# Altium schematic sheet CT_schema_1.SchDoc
size 631 x 630 mm
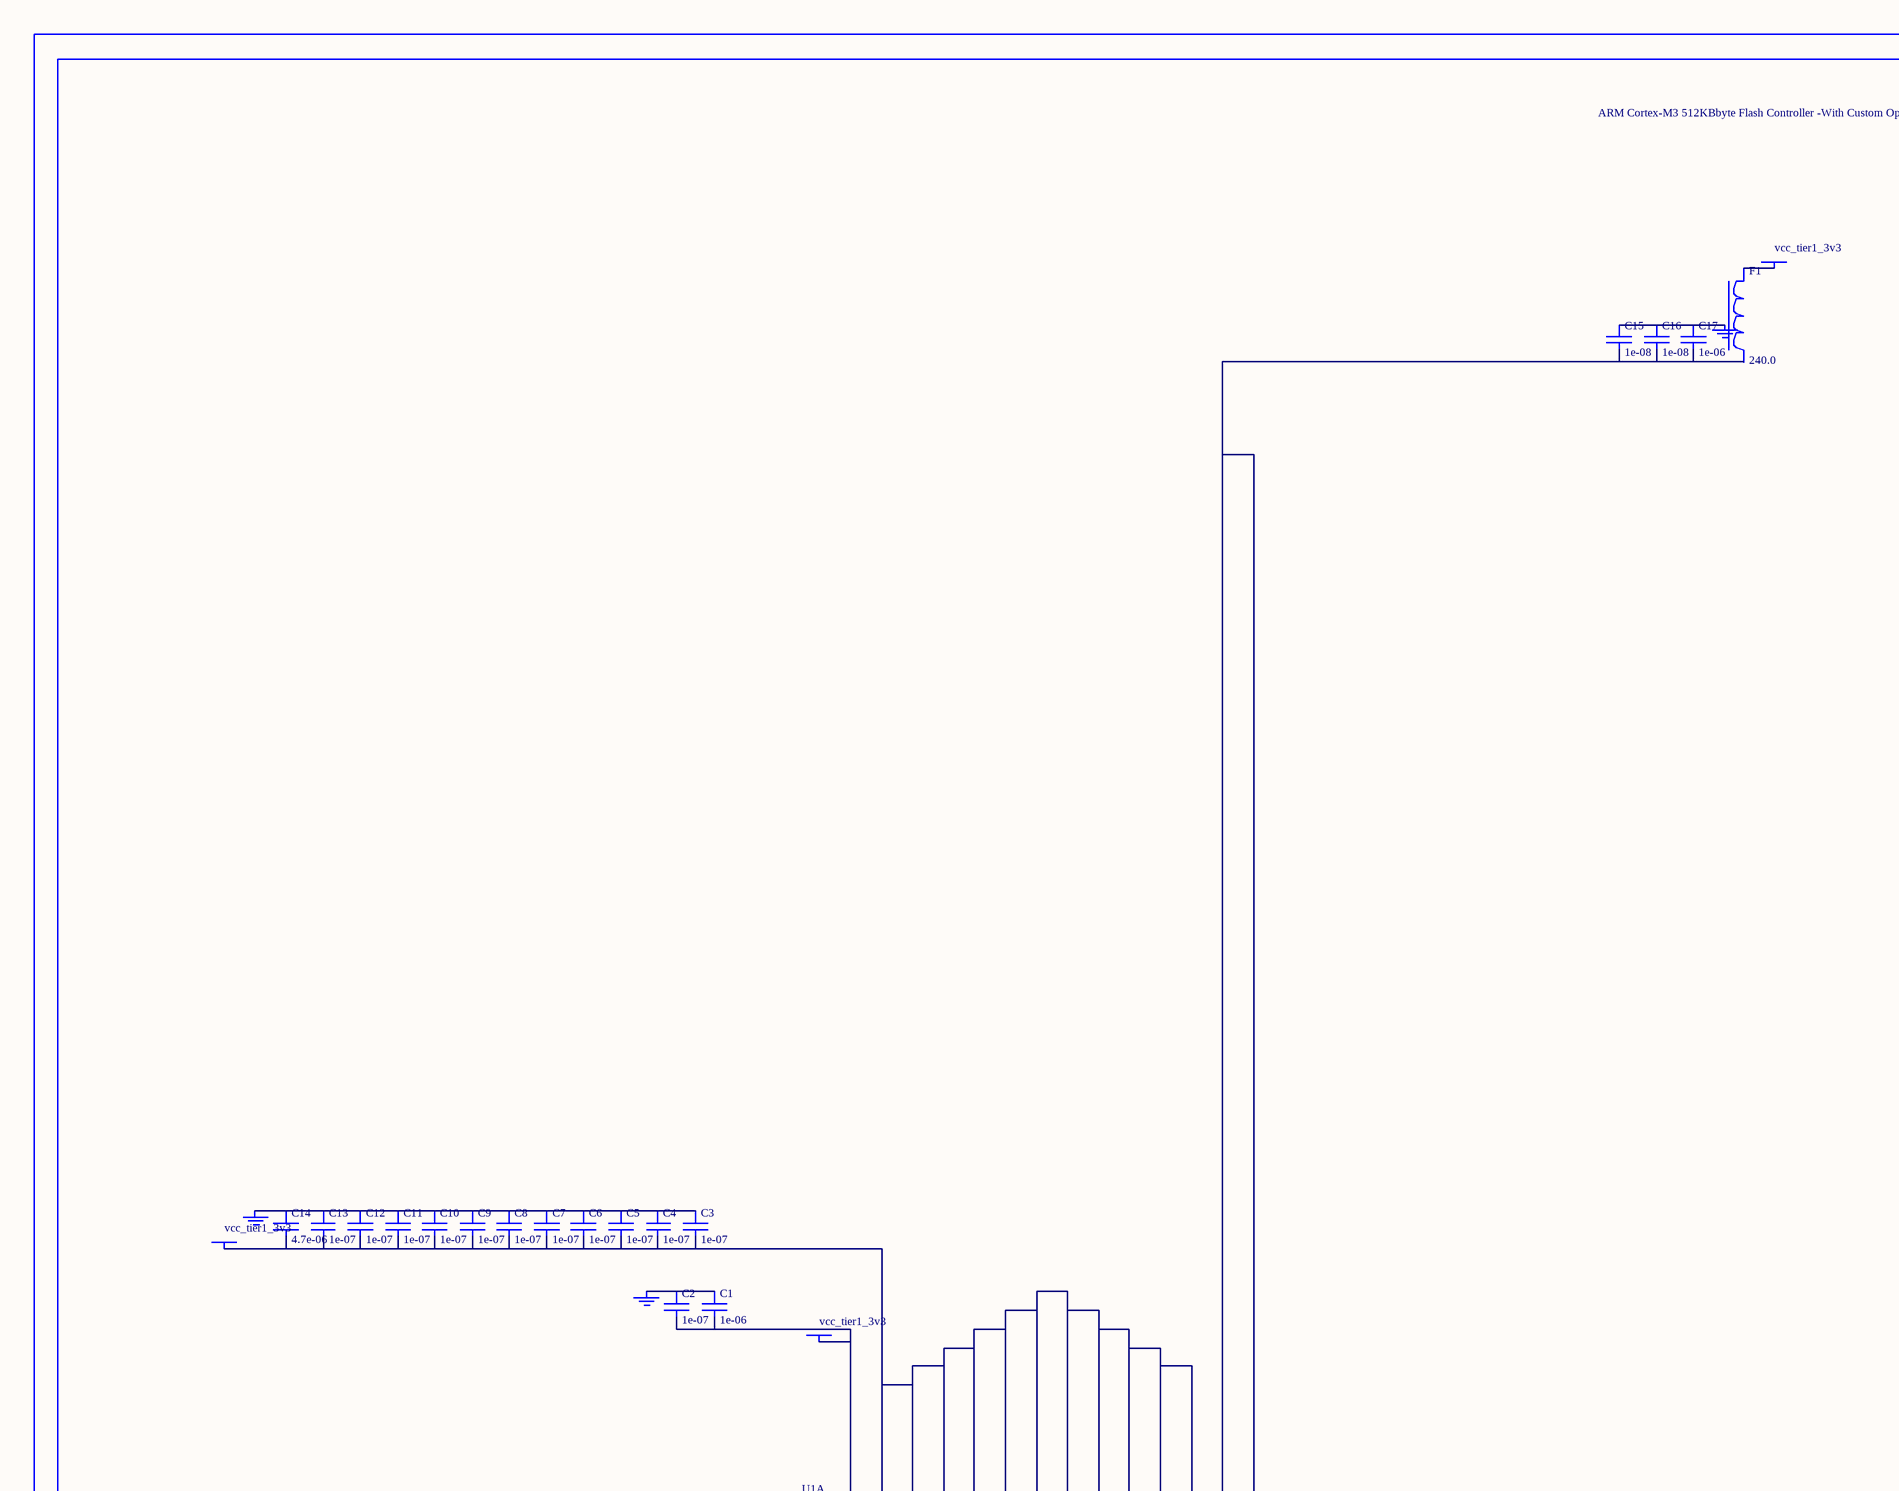
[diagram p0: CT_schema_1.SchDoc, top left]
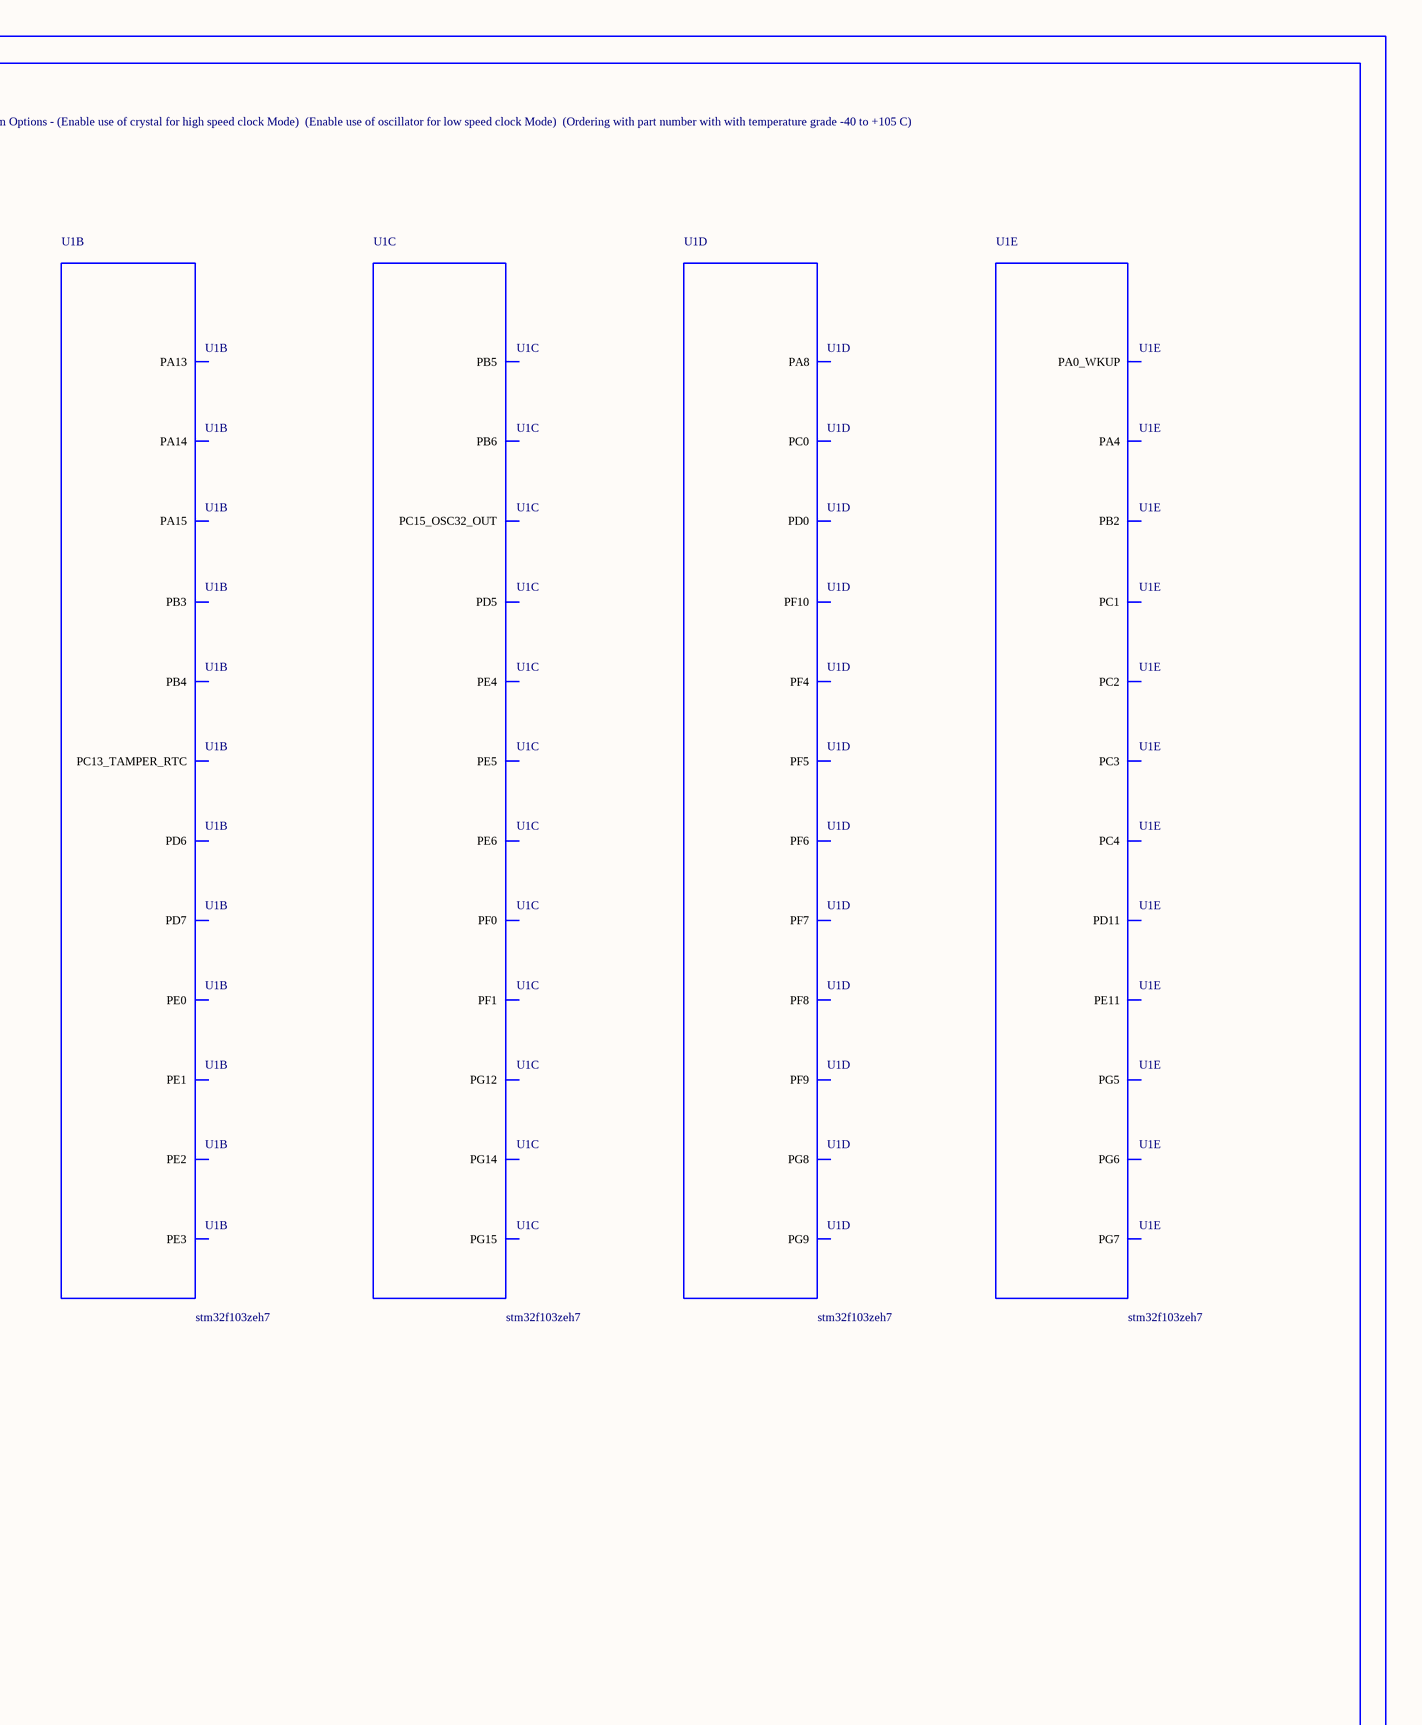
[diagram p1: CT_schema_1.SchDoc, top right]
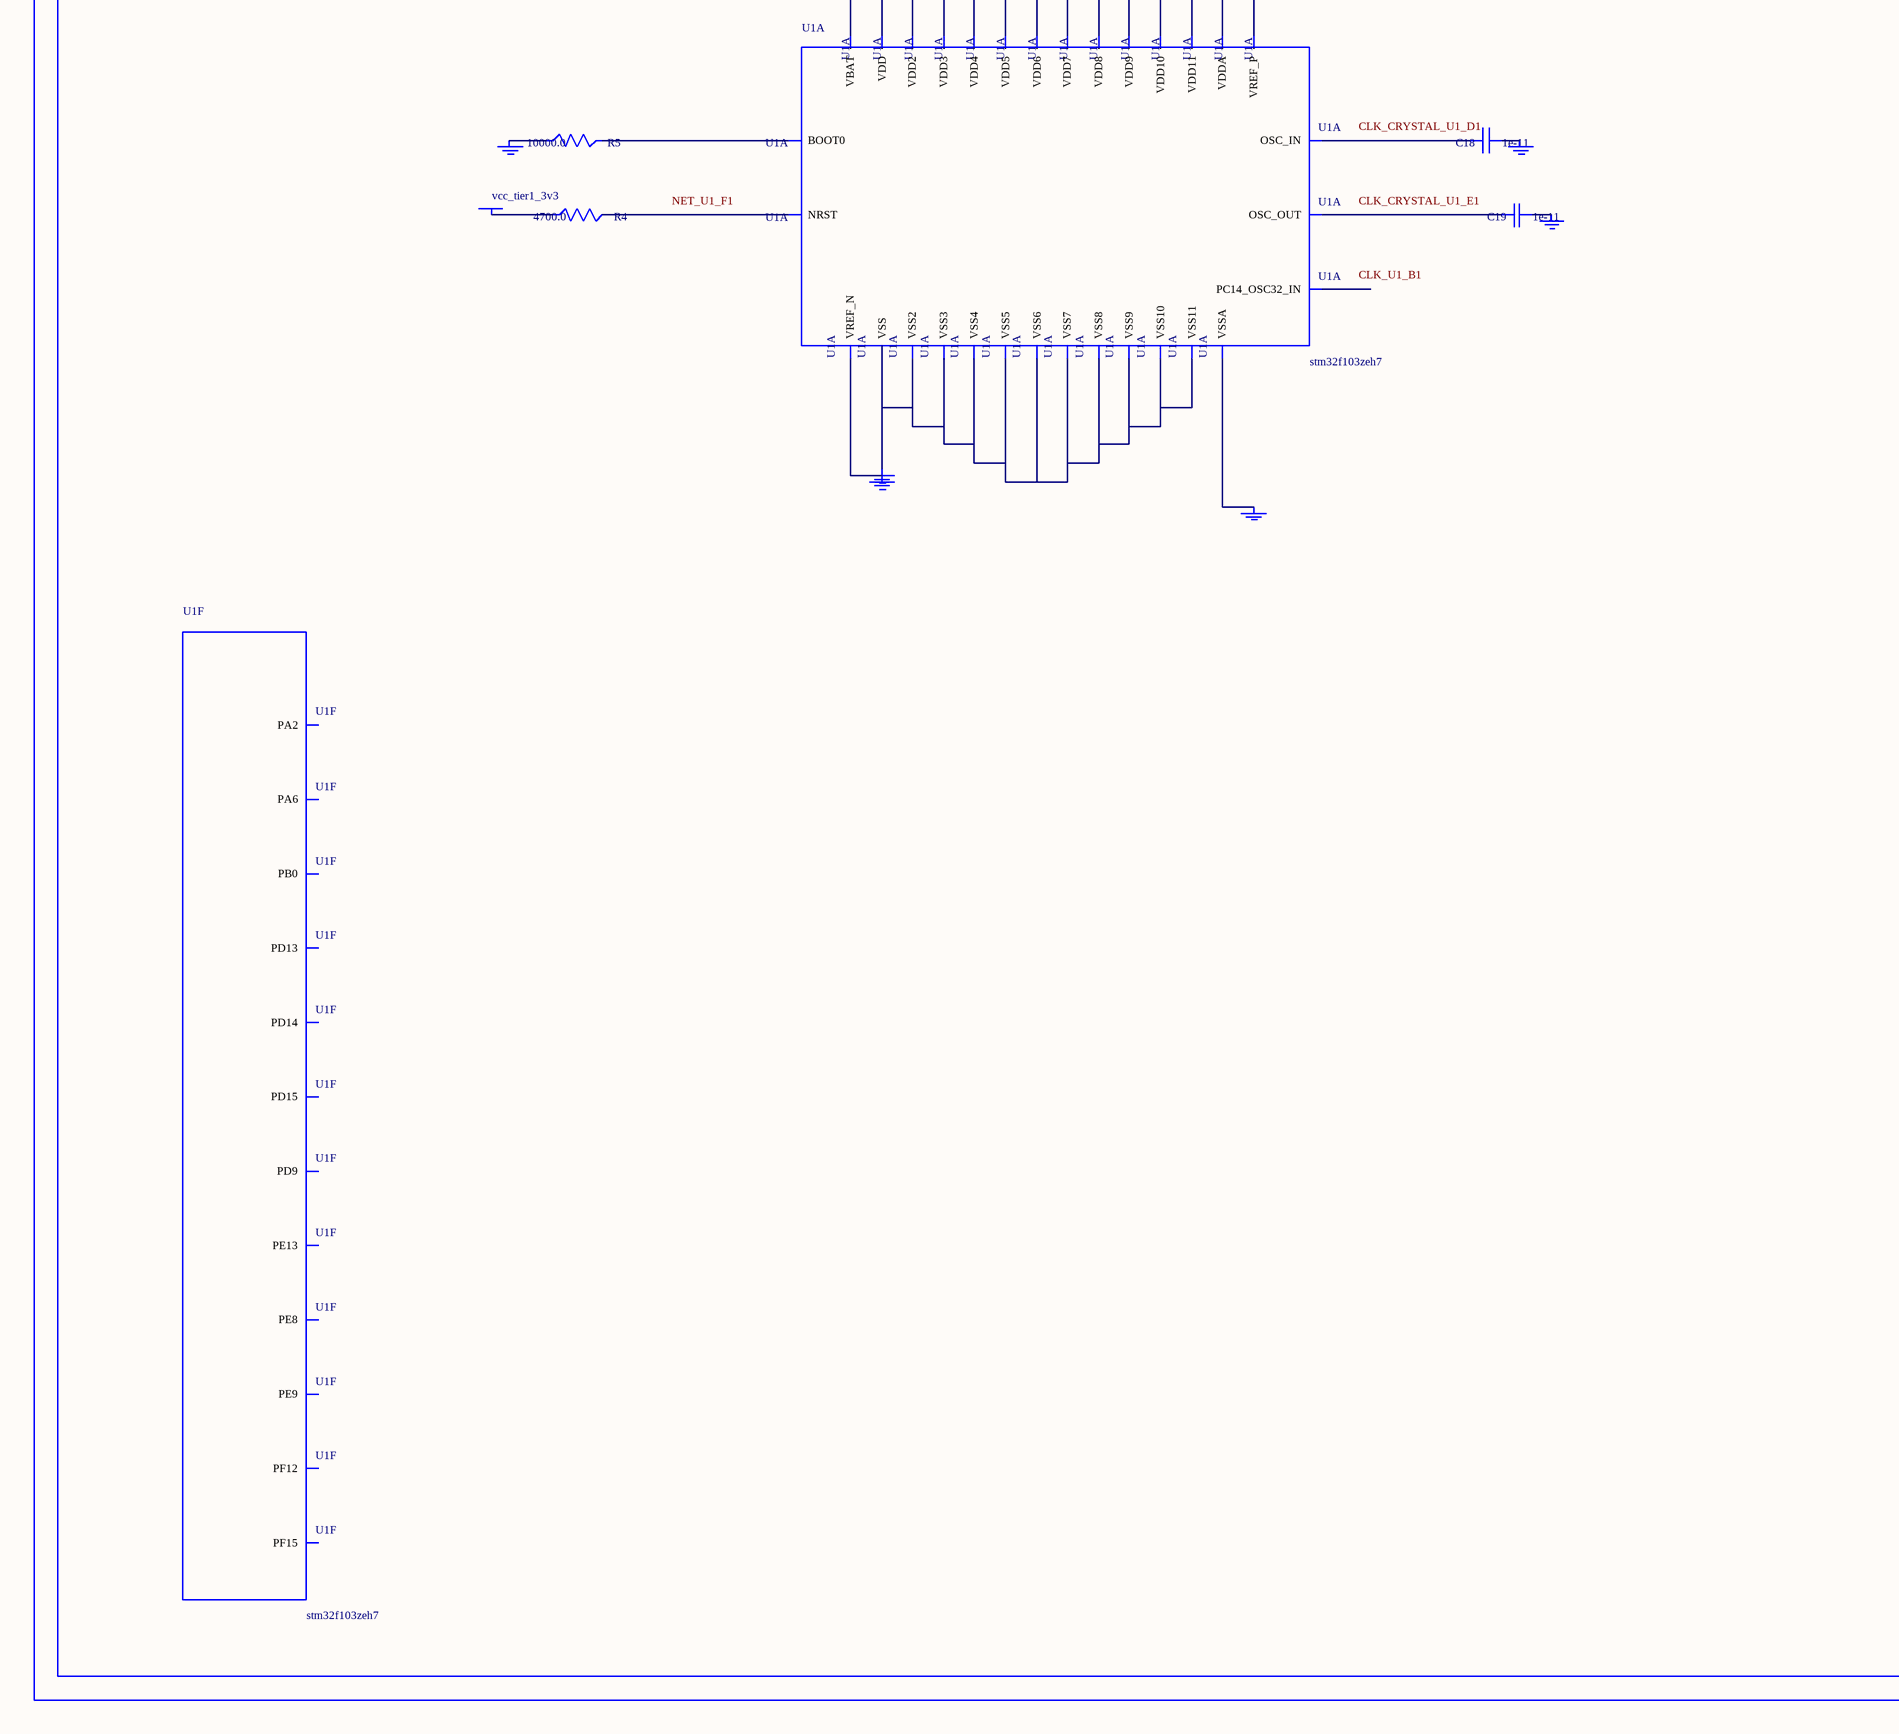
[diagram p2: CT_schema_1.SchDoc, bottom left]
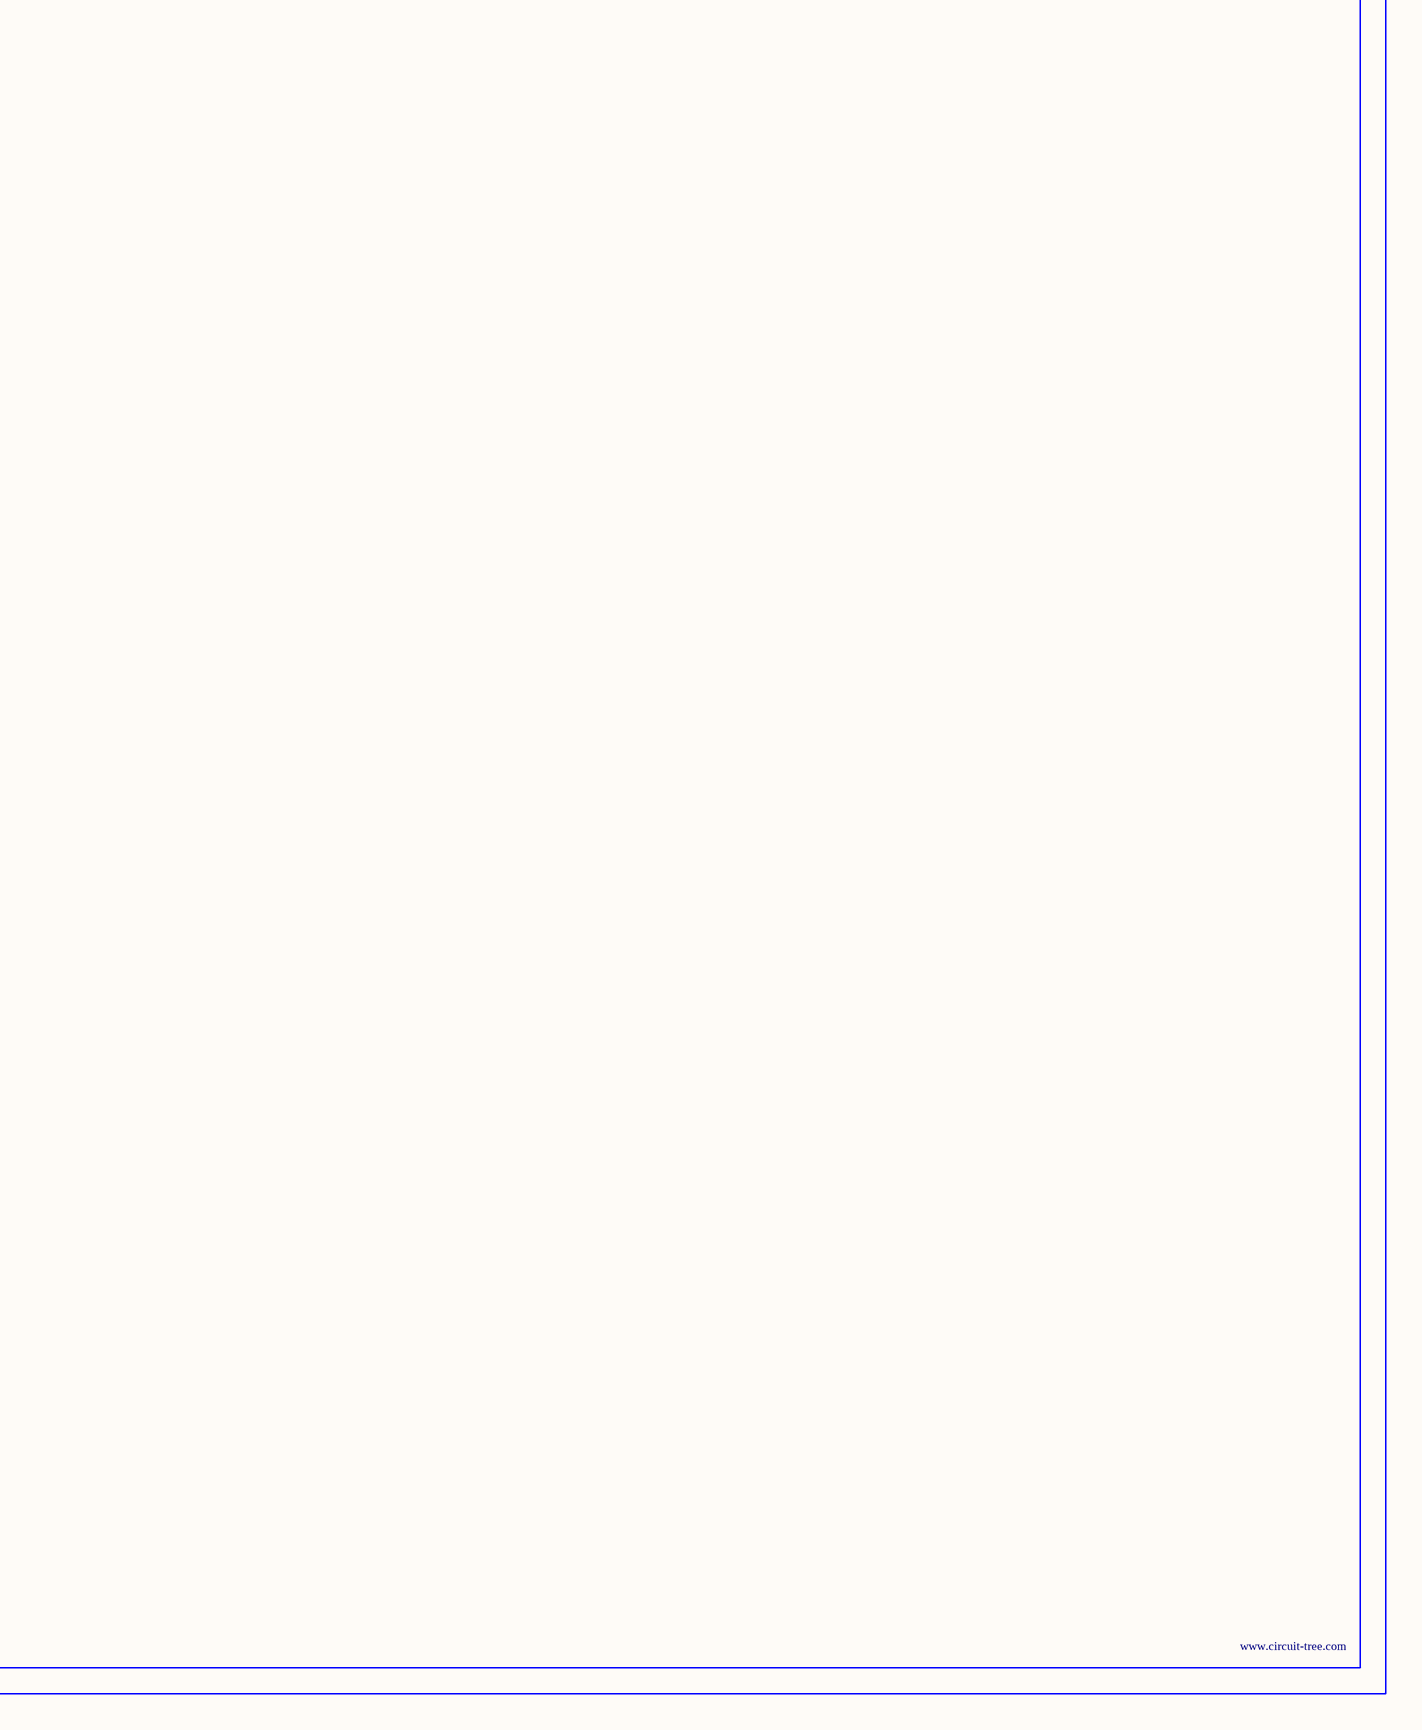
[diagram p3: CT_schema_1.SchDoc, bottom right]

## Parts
BORDER0  (no value)
C1  1e-06  [C0603]
C2  1e-07  [C0603]
C3  1e-07  [C0603]
C4  1e-07  [C0603]
C5  1e-07  [C0603]
C6  1e-07  [C0603]
C7  1e-07  [C0603]
C8  1e-07  [C0603]
C9  1e-07  [C0603]
C10  1e-07  [C0603]
C11  1e-07  [C0603]
C12  1e-07  [C0603]
C13  1e-07  [C0603]
C14  4.7e-06  [C0603]
C15  1e-08  [C0603]
C16  1e-08  [C0603]
C17  1e-06  [C0603]
C18  1e-11  [C0402]
C19  1e-11  [C0402]
F1  240.0  [L0603]
GND_INSTANCE_0_0  (no value)
GND_INSTANCE_0_1  (no value)
GND_INSTANCE_0_2  (no value)
GND_INSTANCE_0_3  (no value)
GND_INSTANCE_0_4  (no value)
GND_INSTANCE_0_5  (no value)
GND_INSTANCE_0_6  (no value)
GND_INSTANCE_0_7  (no value)
GND_INSTANCE_0_8  (no value)
POWER_INSTANCE_0_0  vcc_tier1_3v3
POWER_INSTANCE_0_1  vcc_tier1_3v3
POWER_INSTANCE_0_2  vcc_tier1_3v3
POWER_INSTANCE_0_3  vcc_tier1_3v3
R4  4700.0  [R0603]
R5  10000.0  [R0603]
U1  stm32f103zeh7  [LFBGA144]  (parts A,B,C,D,E,F of 10)

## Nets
NetC1_1: C1.1 C2.1 GND_INSTANCE_0_0.0(GND)
NetC1_2: C1.2 C2.2 POWER_INSTANCE_0_0.0(PWR) U1.C2(VBAT)
NetC3_1: C3.1 C4.1 C5.1 C6.1 C7.1 C8.1 C9.1 C10.1 C11.1 C12.1 C13.1 C14.1 GND_INSTANCE_0_2.0(GND)
NetC3_2: C3.2 C4.2 C5.2 C6.2 C7.2 C8.2 C9.2 C10.2 C11.2 C12.2 C13.2 C14.2 POWER_INSTANCE_0_2.0(PWR) U1.D3(VDD) U1.F4(VDD3) U1.F5(VDD4) U1.F6(VDD5) U1.F7(VDD6) U1.F8(VDD7) U1.F9(VDD8) U1.F10(VDD2) U1.G5(VDD9) U1.G6(VDD10) U1.G7(VDD11)
NetC15_1: C15.1 C16.1 C17.1 GND_INSTANCE_0_1.0(GND)
NetC15_2: C15.2 C16.2 C17.2 U1.L1(VREF_P) U1.M1(VDDA)
NetC18_1: C18.1 GND_INSTANCE_0_4.0(GND)
NetC18_2: C18.2 U1.D1(OSC_IN)
NetC19_1: C19.1 GND_INSTANCE_0_5.0(GND)
NetC19_2: C19.2 U1.E1(OSC_OUT)
NetF1_1: F1.1 POWER_INSTANCE_0_1.0(PWR)
NetGND_INSTANCE_0_3_0: GND_INSTANCE_0_3.0(GND) R5.1
NetGND_INSTANCE_0_6_0: GND_INSTANCE_0_6.0(GND) U1.J1(VSSA)
NetGND_INSTANCE_0_7_0: GND_INSTANCE_0_7.0(GND) U1.K1(VREF_N)
NetGND_INSTANCE_0_8_0: GND_INSTANCE_0_8.0(GND) U1.D2(VSS) U1.E5(VSS2) U1.E6(VSS3) U1.E7(VSS4) U1.G4(VSS6) U1.G8(VSS7) U1.G9(VSS8) U1.G10(VSS5) U1.H5(VSS9) U1.H6(VSS10) U1.H7(VSS11)
NetPOWER_INSTANCE_0_3_0: POWER_INSTANCE_0_3.0(PWR) R4.1
NetR4_2: R4.2 U1.F1(NRST)
NetR5_2: R5.2 U1.D5(BOOT0)

Not connected (* = marked no-connect by the designer): F1 2; U1 A1(PC13_TAMPER_RTC) A2(PE3) A3(PE2) A4(PE1) A5(PE0) A6(PB4) A7(PB3) A8(PD6) A9(PD7) A10(PA15) A11(PA14) A12(PA13) B1(PC14_OSC32_IN) B2(PE4) B3(PE5) B4(PE6) B6(PB5) B7(PG15) B8(PG12) B9(PD5) C1(PC15_OSC32_OUT) C3(PF0) C4(PF1) C6(PB6) C7(PG14) E3(PF4) E4(PF5) E8(PG9) E10(PD0) E12(PA8) F2(PF7) F3(PF6) G1(PF10) G2(PF9) G3(PF8) G11(PG8) H1(PC0) H2(PC1) H3(PC2) H4(PC3) H8(PE11) H9(PD11) H10(PG7) H11(PG6) H12(PG5) J2(PA0_WKUP) J3(PA4) J4(PC4) J5(PB2) K7(PE9) K8(PE13) K9(PD9) K10(PD13) K11(PD14) K12(PD15) L2(PA2) L3(PA6) L4(PB0) L5(PF12) L6(PF15) L7(PE8)

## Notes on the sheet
- Labels drawn without touching a wire or pin: CLK_CRYSTAL_U1_D1, CLK_CRYSTAL_U1_E1, CLK_U1_B1, NET_U1_F1

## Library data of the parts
BORDER0 = BORDER_PAGE0
C1 C17 = C0603C105K3RACTU
C2-C13 = 06035C104K4Z2A
C14 = GRM188R6YA475KE15D
C15 C16 = 06035C103K4Z2A
C18 C19 = C0402C100K3GACTU
F1 = Z0603C241ASMST
GND_INSTANCE_0_0-GND_INSTANCE_0_8 = GND
POWER_INSTANCE_0_0-POWER_INSTANCE_0_3 = PWR
R4 = RC0603JR-074K7L
R5 = RC0603JR-0710KL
